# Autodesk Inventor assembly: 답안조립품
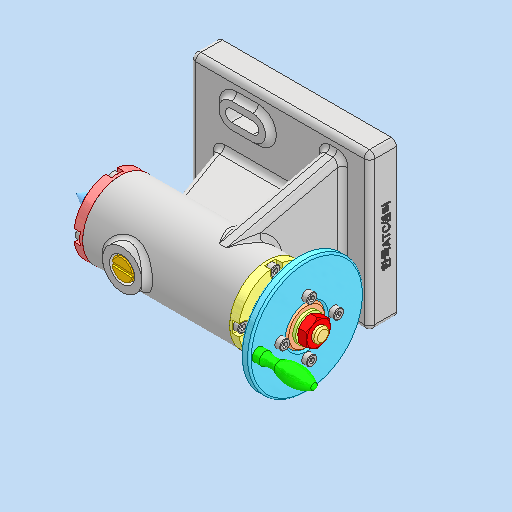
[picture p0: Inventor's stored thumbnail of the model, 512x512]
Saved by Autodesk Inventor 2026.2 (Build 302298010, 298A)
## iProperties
Created: 2026-09
Part Number: 답안조립품
Document SubType Name: Assembly
Designer: PC2-02
Author: PC2-02
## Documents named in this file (18)
- C:\Users\PC2-02\Desktop\760903V1003\답안조립품.iam
- C:\Users\PC2-02\Desktop\760903V1003\부품1.ipt
- C:\Users\PC2-02\Desktop\760903V1003\슬리브\슬리브.ipt
- C:\Users\PC2-02\Desktop\760903V1003\커버\커버.ipt
- C:\Users\PC2-02\Desktop\760903V1003\평 와셔 M8\평 와셔 M8.ipt
- C:\Users\PC2-02\Desktop\760903V1003\평행 키 4x4x10\평행 키 4x4x10.ipt
- C:\Users\PC2-02\Desktop\760903V1003\플랜지\플랜지.ipt
- C:\Users\PC2-02\Desktop\760903V1003\핸들\핸들.ipt
- C:\Users\PC2-02\Desktop\760903V1003\6각 구멍붙이 볼트 M3x8\6각 구멍붙이 볼트 M3x8.ipt
- C:\Users\PC2-02\Desktop\760903V1003\6각 너트 M8\6각 너트 M8.ipt
- C:\Users\PC2-02\Desktop\760903V1003\가이드 부시\가이드 부시.ipt
- C:\Users\PC2-02\Desktop\760903V1003\나사축\나사축.ipt
- C:\Users\PC2-02\Desktop\760903V1003\돌림판\돌림판.ipt
- C:\Users\PC2-02\Desktop\760903V1003\멈춤나사 M3\멈춤나사 M3.ipt
- C:\Users\PC2-02\Desktop\760903V1003\부시\부시.ipt
- C:\Users\PC2-02\Desktop\760903V1003\센터\센터.ipt
- C:\Users\PC2-02\Desktop\760903V1003\센터홀더\센터홀더.ipt
- C:\Users\PC2-02\Desktop\760903V1003\스톱퍼\스톱퍼.ipt
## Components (16 placed, 5 different names)
1. 플랜지:1
2. 핸들:1
3. 6각 구멍붙이 볼트 M3x8:1
4. 6각 너트 M8:1
5. 가이드 부시:1
6. 6각 구멍붙이 볼트 M3x8:2
7. 6각 구멍붙이 볼트 M3x8:3
8. 6각 구멍붙이 볼트 M3x8:4
9. 6각 구멍붙이 볼트 M3x8:5
10. 6각 구멍붙이 볼트 M3x8:6
11. 6각 구멍붙이 볼트 M3x8:7
12. 6각 구멍붙이 볼트 M3x8:8
13. 6각 구멍붙이 볼트 M3x8:9
14. 6각 구멍붙이 볼트 M3x8:10
15. 6각 구멍붙이 볼트 M3x8:11
16. 6각 구멍붙이 볼트 M3x8:12
